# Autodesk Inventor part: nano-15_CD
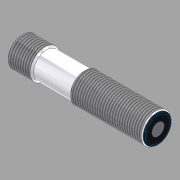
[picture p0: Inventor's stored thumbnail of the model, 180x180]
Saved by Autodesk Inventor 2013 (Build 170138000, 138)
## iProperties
Shininess: 20.0
Length Units: 11269
Angle Units: 11279
Time Units: 11290
Mass Units: 11283
Length Display Precision: 2
Angle Display Precision: 2
Part Number: nano-15_CD
Material: Nichtrostender Stahl - 440C
Document SubType Name: Modellieren
Description: Ipc-25 /CXX/M18
Checked By: Alves
Created: 2005-08
Designer: Ohle
Manufacturer: Standard
Standards Organization: Custom
Density: 0.0
Volumn: 0.0
Area: 0.0
PropertySet Name: Model Information
Control State: 0
Master: False
Checked Out: False
BESTELLNUMMER: Ipc-25 /CXX/M18
ME: ST
Title: Ipc Sensoren
Author: Ohle
Comments: keine Bemerkung
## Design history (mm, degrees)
sketch "Skizze10"
  geometry: L1 (-42.478, 0)-(4.622, 0); L2 (-45.9, 8)-(-45.9, 8); L3 (-24.778, 6)-(3.722, 6); L4 (4.612, 4.75)-(4.612, 2.5); L5 (4.612, 2.5)-(4.622, 2.5); L6 (4.622, 2.5)-(4.622, 0); L7 (4.622, 0)-(-82, 0); L8 (1.522, 8.25)-(1.522, 8.25); L9 (-25.478, 5.3)-(-24.778, 6); L10 (4.122, 5.6)-(3.722, 6); L11 (-49.978, 6)-(-41.178, 6); L12 (-40.478, 5.3)-(-25.478, 5.3); L13 (-50.478, 4.5)-(-42.478, 4.5); L14 (-42.478, 0)-(-42.478, 4.5); L15 (4.122, 5.6)-(4.322, 5.6); L16 (-50.478, 5.5)-(-50.478, 4.5); L17 (-50.478, 5.5)-(-49.978, 6); L18 (4.622, 5.3)-(4.622, 4.75); L19 (4.622, 4.75)-(4.612, 4.75); L20 (-41.178, 6)-(-40.478, 5.3); A1 r 0.3 centre (4.322, 5.3) between (4.622, 5.3) and (4.322, 5.6); 3 further points
  constraints: 40 end point, 5 point on line, 3 perpendicular, 2 horizontal, 2 parallel, 2 point on circle, 1 centre point, 1 collinear, 1 tangent
  dimensions: "d136" = 2.5 distance of L5.end L1.end; "d138" = 6 distance between parallel lines of L3 L7; "d171" = 4.5 distance between parallel lines of L13 L1; "d256" = 45 deg angle of L3 L9; "d269" = 6 distance between parallel lines of L7 L11; "d289" = 135 deg angle of L10 L3; "d293" = 0.5 horizontal distance of L16.start L11.start; "d294" = 45 deg angle of L17 L11 (derived); "d295" = 8 distance of L13.start L13.end; "d331" = 0.01 distance between parallel lines of L4 L6; "d335" = 0.3 radius of A1; "d338" = 0.01 distance between parallel lines of L18 L4; "d339" = 4.75 distance between parallel lines of L7 L19; "d340" = 5.3 distance between parallel lines of L1 L12; "d341" = 10 distance from line of L12.start L16; "d343" = 135 deg angle of L20 L11; "d347" = 0.2 distance of L10.start L15.end; "d348" = 25 distance from line of L9.start L16; "d349" = 54.6 distance from line of L10.start L16; "d350" = 5.6 distance between parallel lines of L15 L7
revolve "Grundkörper pico+" sketch "Skizze10" stored, may be unused: angle "d168" = 90 deg
sketch "Skizze13"
  geometry: L1 (-3.409, -3.409)-(3.61, 3.61); L2 (-3.439, 3.439)-(4.105, -4.105); L3 (-8.4, 0)-(8.4, 0) reference; C1 r 0.5 at (2.121, -2.121); C2 r 0.5 at (2.121, 2.121); C3 r 0.5 at (-2.121, 2.121); C4 r 0.5 at (-2.121, -2.121); C5 r 4.5 at (0, 0) reference; C6 r 0.5 at (0, 0); A1 r 3 centre (0, 0) between (-2.121, 2.121) and (2.121, 2.121); 2 further points
  constraints: 6 centre point, 6 point on line, 4 coincident, 4 end point, 4 equal radius, 4 point on circle, 1 horizontal alignment, 1 perpendicular
  dimensions: "d208" = 1 diameter of C3; "d209" = 6 diameter of A1
extrude "Pole" join sketch "Skizze13" distance "d212" = 7; taper "d213" = 0 deg
fillet "Rundung Pole" dims "d214" = 0.5
sketch "Skizze14"
  geometry: C1 r 0.5 at (0, -4.5); A1 r 4.5 centre (0, 0) between (4.435, -0.762) and (4.435, 0.762); A2 r 4.5 centre (0, 0) between (0, 4.5) and (0.499, 4.472) reference; A3 r 0.5 centre (0, 4.5) between (-0.499, 4.472) and (0.499, 4.472); 3 further points
  constraints: 9 point on circle, 3 centre point, 3 coincident, 1 horizontal alignment, 1 vertical alignment
  dimensions: "d215" = 9 diameter of A1; "d280" = 1 diameter of A3; "d330" = 1 diameter of C1
extrude "Verdrehsicherung" join sketch "Skizze14" distance "d217" = 7.9; taper "d218" = 0 deg
feature "Gewinde7" dims "d351" = 10, "d352" = 0
feature "Gewinde8" dims "d353" = 10, "d354" = 0
node "Volumenkörper1"
node "Volumenkörper"
node "Oberflächenkörper"
other parameters: "d10" = 14, "d130" = 0.2
